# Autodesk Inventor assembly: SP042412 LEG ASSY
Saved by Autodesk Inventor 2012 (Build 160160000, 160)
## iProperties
Created: 2013-04
Part Number: SP042412 LEG ASSY
Document SubType Name: Assembly
Designer: Admin
Author: Admin
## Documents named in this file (3)
- C:\Andys Backup Data\ANDY'S INVENTOR\INVENTOR LIBRARIES\ASSEMBLY LIBRARY\45 SERIES\TABLES_CARTS\SP042413 45X45UL\SP042412 LEG ASSY.iam
- C:\Andys Backup Data\ANDY'S INVENTOR\INVENTOR LIBRARIES\ASSEMBLY LIBRARY\45 SERIES\TABLES_CARTS\SP042413 45X45UL\SP042413 LEG.ipt
- C:\Andys Backup Data\ANDY'S INVENTOR\INVENTOR LIBRARIES\PARTS LIBRARY\FEET WHEELS FLOOR FASTENING SUPPORTS\21.9402 CASTER 3.5 BRK.iam
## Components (2 placed, 2 different names)
1. SP042413 LEG:1
2. 21.9402 CASTER 3.5 BRK:1 [sub-assembly]
## Named parameters: d0_d1 = 0
